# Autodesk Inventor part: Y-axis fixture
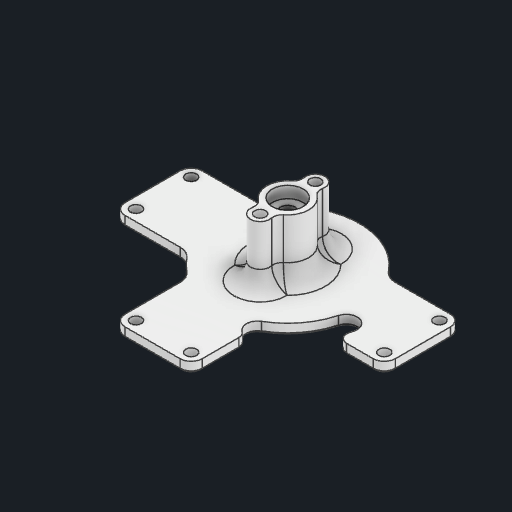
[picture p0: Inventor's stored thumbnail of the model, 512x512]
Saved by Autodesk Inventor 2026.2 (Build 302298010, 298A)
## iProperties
Created: 2026-04
Part Number: Y-axis fixture
Material: PBT 플라스틱
Document SubType Name: Modeling
Designer: work
Density: 1.31 g/cm^3
Appearance: 매끄러움 - 흰색
Author: work
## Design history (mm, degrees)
sketch "스케치1"
  geometry: L1 (25.93, 32.053)-(32.053, 25.93); L2 (25.46, 31.583)-(25.93, 32.053); L3 (-10, 49)-(10, 49); L4 (-49, -10)-(-49, 10); L5 (10, -99)-(-10, -99); L6 (32.053, 25.93)-(31.583, 25.46); L7 (49, 10)-(49, -10); L8 (-45, 14)-(-30.984, 14); L9 (-45, -14)-(-21.909, -14); L10 (45, 14)-(21.909, 14); L11 (-14, 45)-(-14, 29.854); L12 (14, 45)-(14, 21.909); L13 (45, -14)-(21.909, -14); C1 r 2 at (-15.5, -39.5); C2 r 12.5 at (0, -55); C3 r 2 at (15.5, -39.5); C4 r 2 at (-10, 45); C5 r 2 at (10, 45); C6 r 2 at (-45, 10); C7 r 2 at (-45, -10); C8 r 2 at (-15.5, -70.5); C9 r 2 at (15.5, -70.5); C10 r 2 at (10, -95); C11 r 2 at (-10, -95); C12 r 2 at (45, -10); C13 r 2 at (45, 10); C14 r 6.25 at (0, 0); C15 r 2.65 at (0, 0); A1 r 2 centre (-6.237, -29.344) between (-6.653, -31.301) and (-5.822, -27.388); A2 r 29 centre (0, -55) between (22.73, -73.009) and (27.61, -46.129); A3 r 28 centre (0, 0) between (-21.449, -17.998) and (-5.822, -27.388); A4 r 32 centre (0, 0) between (-24.513, -20.569) and (-6.653, -31.301); A5 r 31 centre (-57.124, -36.646) between (-27.61, -46.129) and (-29.816, -21.973); A6 r 29 centre (0, -55) between (-27.61, -46.129) and (-22.73, -73.009); A7 r 2 centre (6.237, -29.344) between (5.822, -27.388) and (6.653, -31.301); A8 r 28 centre (0, 0) between (5.822, -27.388) and (21.449, -17.998); A9 r 2 centre (22.981, -19.284) between (24.513, -20.569) and (21.449, -17.998); A10 r 31 centre (57.124, -36.646) between (29.816, -21.973) and (27.61, -46.129); A11 r 4 centre (-10, 45) between (-10, 49) and (-14, 45); A12 r 7 centre (24.375, 36.853) between (19.425, 31.903) and (20.306, 31.156); A13 r 4 centre (10, 45) between (14, 45) and (10, 49); A14 r 4 centre (22.631, 34.411) between (20.306, 31.156) and (25.46, 31.583); A15 r 18.522 centre (32.522, 45) between (14, 45) and (19.425, 31.903); A16 r 18.522 centre (-45, 32.522) between (-45, 14) and (-29.988, 21.673); A17 r 4 centre (-45, 10) between (-45, 14) and (-49, 10); A18 r 4 centre (-45, -10) between (-49, -10) and (-45, -14); A19 r 18.522 centre (-45, -32.522) between (-30.128, -21.482) and (-45, -14); A20 r 4 centre (-33.339, -23.867) between (-29.816, -21.973) and (-30.128, -21.482); A21 r 2 centre (-22.981, -19.284) between (-21.449, -17.998) and (-24.513, -20.569); A22 r 41 centre (-54.866, -98.471) between (-13.988, -95.309) and (-22.73, -73.009); A23 r 4 centre (-10, -95) between (-13.988, -95.309) and (-10, -99); A24 r 41 centre (54.866, -98.471) between (22.73, -73.009) and (13.988, -95.309); A25 r 4 centre (10, -95) between (10, -99) and (13.988, -95.309); A26 r 4 centre (33.339, -23.867) between (30.128, -21.482) and (29.816, -21.973); A27 r 18.522 centre (45, -32.522) between (45, -14) and (30.128, -21.482); A28 r 4 centre (45, -10) between (45, -14) and (49, -10); A29 r 4 centre (34.411, 22.631) between (31.583, 25.46) and (31.156, 20.306); A30 r 7 centre (36.853, 24.375) between (31.156, 20.306) and (31.903, 19.425); A31 r 18.522 centre (45, 32.522) between (31.903, 19.425) and (45, 14); A32 r 4 centre (45, 10) between (49, 10) and (45, 14); A33 r 32 centre (0, 0) between (6.653, -31.301) and (24.513, -20.569); A34 r 18.522 centre (-32.522, 45) between (-21.673, 29.988) and (-14, 45); A35 r 37 centre (0, 0) between (-21.673, 29.988) and (-29.988, 21.673); A36 r 26 centre (0, 0) between (-13, 22.517) and (-25.114, 6.729); A37 r 34 centre (0, 0) between (-17, 29.445) and (-32.841, 8.8); A38 r 4 centre (-28.978, 7.765) between (-32.841, 8.8) and (-25.114, 6.729); A39 r 4 centre (-15, 25.981) between (-13, 22.517) and (-17, 29.445); A40 r 26 centre (0, 0) between (-21.909, -14) and (21.909, 14); 2 further points
  constraints: 84 point on circle, 55 centre point, 26 end point, 3 tangent, 2 coincident, 2 horizontal, 2 parallel, 1 point on line, 1 vertical
  dimensions: "d2" = 5.3 diameter of C15
extrude "돌출1" new body sketch "스케치1" distance "d0" = 4; taper "d1" = 0 deg
sketch "스케치2"
  geometry: L1 (-10, -49)-(10, -49) reference; L2 (14, -45)-(14, -29.854) reference; L3 (30.984, -14)-(45, -14) reference; L4 (49, -10)-(49, 10) reference; L5 (45, 14)-(21.909, 14) reference; L6 (-21.909, 14)-(-45, 14) reference; L7 (-49, 10)-(-49, -10) reference; L8 (-45, -14)-(-21.909, -14) reference; L9 (-14, -21.909)-(-14, -45) reference; L10 (0, 0)-(0, -10); L11 (0, -10)-(0, 0); L12 (0, 0)-(0, 10); C1 r 2 at (45, -10) reference; C2 r 2 at (45, 10) reference; C3 r 2 at (-45, -10) reference; C4 r 2 at (-45, 10) reference; C5 r 2 at (-10, -45) reference; C6 r 2 at (10, -45) reference; C7 r 2.65 at (0, 0) reference; C8 r 7.6 at (0, 0); C9 r 5.6 at (0, 0); C10 r 2 at (0, -10); C11 r 2 at (0, 10); C12 r 3.5 at (0, -10); C13 r 3.5 at (0, 10); A1 r 4 centre (10, -45) between (10, -49) and (14, -45) reference; A2 r 4 centre (15, -25.981) between (13, -22.517) and (14, -29.854) reference; A3 r 26 centre (0, 0) between (13, -22.517) and (25.114, -6.729) reference; A4 r 4 centre (28.978, -7.765) between (32.841, -8.8) and (25.114, -6.729) reference; A5 r 34 centre (0, 0) between (30.984, -14) and (32.841, -8.8) reference; A6 r 4 centre (45, -10) between (45, -14) and (49, -10) reference; A7 r 4 centre (45, 10) between (49, 10) and (45, 14) reference; A8 r 26 centre (0, 0) between (21.909, 14) and (-21.909, 14) reference; A9 r 4 centre (-45, 10) between (-45, 14) and (-49, 10) reference; A10 r 4 centre (-45, -10) between (-49, -10) and (-45, -14) reference; A11 r 26 centre (0, 0) between (-21.909, -14) and (-14, -21.909) reference; A12 r 4 centre (-10, -45) between (-14, -45) and (-10, -49) reference; 5 further points
  constraints: 6 centre point, 6 end point, 4 coincident, 2 vertical, 1 collinear
  dimensions: "d3" = 11.2 diameter of C9; "d4" = 2 radial gap between concentric circles of C8 C9; "d5" = 4 diameter of C10; "d6" = 4 diameter of C11; "d7" = 10 distance of L10.end L10.start; "d8" = 10 distance of L10.start L12.end; "d9" = 7 diameter of C12; "d10" = 7 diameter of C13
extrude "돌출2" join sketch "스케치2" distance "d11" = 21; taper "d12" = 0 deg
sketch "스케치3"
  geometry: C1 r 5.6 at (0, 0); 1 further point
  constraints: 1 centre point, 1 coincident
  dimensions: "d13" = 11.2 diameter of C1
extrude "돌출3" cut sketch "스케치3" distance "d14" = 4.2; taper "d15" = 0 deg
fillet "모깎기1" dims "d16" = 3
fillet "모깎기2" dims "d17" = 6
chamfer "모따기1" distance "d18" = 1; stored, may be unused: second distance "d19" = 2, angle "d20" = 45 deg
feature "̋耀̍耀̏耀̑耀̓耀̕耀̗耀̙耀" dims "d0" = 4, "d1" = 0, "d2" = 5.3, "d3" = 11.2, "d4" = 2, "d5" = 4, "d6" = 4, "d7" = 10, "d8" = 10, "d9" = 7, "d10" = 7, "d11" = 21, "d12" = 0, "d13" = 11.2, "d14" = 4.2, "d15" = 0, "d16" = 3, "d17" = 6, "d18" = 1, "d19" = 2, "d20" = 45 deg
node "솔리드1"
node "투영된 루프1"
